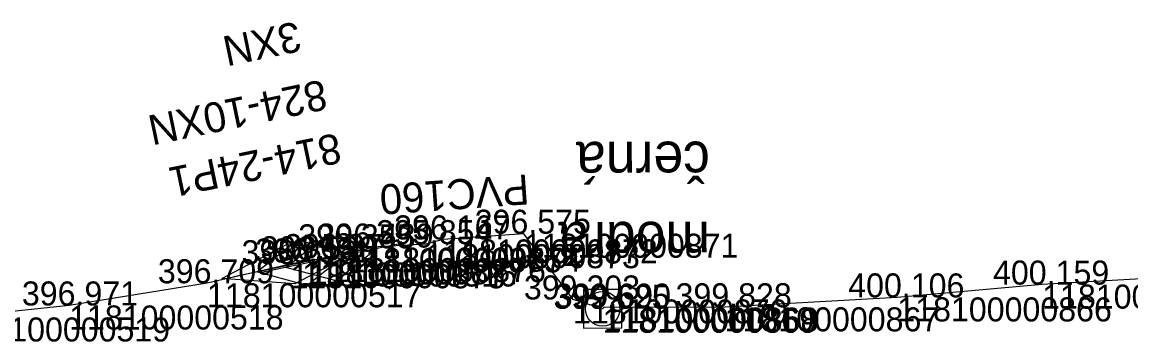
# Model space of a CAD drawing. Extents: x -727171 to -722443, y -945718 to -941834.
# Drawn here: x -723400.7 to -723345.4, y -945339 to -945323 of the extents above; entities that cross this region are included whole.
import ezdxf

# ---------------------------------------------------------------- set-up
doc = ezdxf.new("R2010")
doc.units = 0
for name, color, linetype in [('Vrstva 28', 7, 'Continuous'), ('Vrstva 31', 7, 'Continuous'), ('Vrstva 33', 7, 'Continuous'), ('Vrstva 35', 7, 'Continuous'), ('Vrstva 60', 7, 'Continuous'), ('Vrstva 61', 7, 'Continuous')]:
    doc.layers.add(name, color=color, linetype=linetype)

msp = doc.modelspace()

# ---------------------------------------------------------------- linework, layer by layer
at = {"layer": 'Vrstva 28'}
for p, q in [((-723389.019, -945335.496), (-723386.978, -945333.883)), ((-723387.569, -945335.276), (-723385.528, -945333.663)), ((-723386.978, -945333.883), (-723384.463, -945334.55)), ((-723385.528, -945333.663), (-723383.013, -945334.33)), ((-723383.323, -945334.314), (-723390.159, -945335.732)), ((-723381.873, -945334.094), (-723388.709, -945335.512)), ((-723384.463, -945334.55), (-723386.504, -945336.163)), ((-723383.013, -945334.33), (-723385.054, -945335.943)), ((-723386.504, -945336.163), (-723389.019, -945335.496)), ((-723385.054, -945335.943), (-723387.569, -945335.276))]:
    msp.add_line(p, q, dxfattribs=at)
msp.add_lwpolyline([(-723330.159, -945335.46), (-723333.207, -945336.035), (-723333.428, -945336.077), (-723338.468, -945336.674), (-723341.942, -945335.667), (-723349.803, -945336.126), (-723357.035, -945336.766), (-723365.653, -945337.261), (-723371.687, -945337.277), (-723371.747, -945337.334), (-723373.227, -945336.869), (-723375.679, -945333.586), (-723379.704, -945333.869), (-723380.6, -945334.107), (-723383.538, -945334.276), (-723384.488, -945334.317), (-723385.291, -945334.803), (-723386.372, -945334.912), (-723386.741, -945335.023), (-723387.326, -945335.11), (-723391.5, -945336.06), (-723398.387, -945337.169), (-723404.052, -945337.768)], dxfattribs=at)
at = {"layer": 'Vrstva 31'}
for points in [[(-723330.159, -945335.46), (-723333.207, -945336.035), (-723333.428, -945336.077), (-723338.468, -945336.674), (-723341.942, -945335.667), (-723349.803, -945336.126), (-723357.035, -945336.766), (-723365.653, -945337.261), (-723371.687, -945337.277), (-723371.747, -945337.334), (-723373.227, -945336.869), (-723375.679, -945333.586), (-723379.704, -945333.869), (-723380.6, -945334.107), (-723383.538, -945334.276), (-723384.488, -945334.317), (-723385.291, -945334.803), (-723386.372, -945334.912), (-723387.326, -945335.11), (-723391.5, -945336.06), (-723398.387, -945337.169), (-723404.052, -945337.768)], [(-723383.899, -945334.399), (-723387.123, -945336.089), (-723390.753, -945335.821), (-723387.529, -945334.131), (-723383.899, -945334.399)]]:
    msp.add_lwpolyline(points, dxfattribs=at)
at = {"layer": 'Vrstva 33'}
msp.add_lwpolyline([(-723341.942, -945335.667), (-723349.803, -945336.126), (-723357.035, -945336.766), (-723365.653, -945337.261), (-723371.687, -945337.277), (-723371.747, -945337.334), (-723373.227, -945336.869), (-723375.679, -945333.586), (-723379.704, -945333.869), (-723380.6, -945334.107), (-723383.538, -945334.276), (-723384.488, -945334.317), (-723385.291, -945334.803), (-723386.372, -945334.912), (-723387.326, -945335.11), (-723391.5, -945336.06), (-723398.387, -945337.169), (-723404.052, -945337.768)], dxfattribs=at)
msp.add_lwpolyline([(-723370.79, -945336.371), (-723372.71, -945336.377), (-723372.704, -945338.297), (-723370.784, -945338.291)], close=True, dxfattribs=at)
msp.add_circle((-723371.747, -945337.334), 0.864, dxfattribs=at)
at = {"layer": 'Vrstva 35'}
msp.add_lwpolyline([(-723371.747, -945337.334), (-723373.227, -945336.869), (-723375.679, -945333.586), (-723379.704, -945333.869), (-723380.6, -945334.107), (-723383.538, -945334.276), (-723384.488, -945334.317)], dxfattribs=at)
at = {"layer": 'Vrstva 60'}
for p, q in [((-723379.704, -945333.869), (-723379.704, -945333.869)), ((-723375.679, -945333.586), (-723375.679, -945333.586)), ((-723384.488, -945334.317), (-723384.488, -945334.317)), ((-723383.538, -945334.276), (-723383.538, -945334.276)), ((-723380.6, -945334.107), (-723380.6, -945334.107)), ((-723387.326, -945335.11), (-723387.326, -945335.11)), ((-723386.741, -945335.023), (-723386.741, -945335.023)), ((-723386.372, -945334.912), (-723386.372, -945334.912)), ((-723385.291, -945334.803), (-723385.291, -945334.803)), ((-723391.5, -945336.06), (-723391.5, -945336.06)), ((-723349.803, -945336.126), (-723349.803, -945336.126)), ((-723357.035, -945336.766), (-723357.035, -945336.766)), ((-723398.387, -945337.169), (-723398.387, -945337.169)), ((-723373.227, -945336.869), (-723373.227, -945336.869)), ((-723371.747, -945337.334), (-723371.747, -945337.334)), ((-723371.687, -945337.277), (-723371.687, -945337.277)), ((-723365.653, -945337.261), (-723365.653, -945337.261))]:
    msp.add_line(p, q, dxfattribs=at)

# ---------------------------------------------------------------- texts
at = {"layer": 'Vrstva 28'}
for s, p in [('3XN', (-723386.993, -945322.968)), ('814-24P1', (-723384.986, -945328.543))]:
    msp.add_text(s, height=1.5, rotation=191.7251, dxfattribs=at).set_placement(p)
at = {"layer": 'Vrstva 31'}
msp.add_text('824-10XN', height=1.5, rotation=191.7251, dxfattribs=at).set_placement((-723385.698, -945325.874))
at = {"layer": 'Vrstva 33'}
for s, p in [('černá', (-723366.392, -945328.981)), ('modrá', (-723366.381, -945332.981))]:
    msp.add_text(s, height=2, rotation=180.1519, dxfattribs=at).set_placement(p)
at = {"layer": 'Vrstva 35'}
msp.add_text('PVC160', height=1.5, rotation=184.0219, dxfattribs=at).set_placement((-723375.473, -945330.615))
at = {"layer": 'Vrstva 60'}
for s, p in [('118100000872', (-723379.704, -945335.069)), ('118100000871', (-723375.679, -945334.786)), ('118100000875', (-723384.488, -945335.517)), ('118100000874', (-723383.538, -945335.476)), ('118100000873', (-723380.6, -945335.307)), ('118100000878', (-723387.326, -945336.31)), ('118100000516', (-723386.741, -945336.223)), ('118100000877', (-723386.372, -945336.112)), ('118100000876', (-723385.291, -945336.003)), ('118100000517', (-723391.5, -945337.26)), ('118100000865', (-723349.803, -945337.326)), ('118100000866', (-723357.035, -945337.966)), ('118100000518', (-723398.387, -945338.369)), ('118100000870', (-723373.227, -945338.069)), ('118100000869', (-723371.747, -945338.534)), ('118100000868', (-723371.687, -945338.477)), ('118100000867', (-723365.653, -945338.461)), ('118100000519', (-723404.052, -945338.968))]:
    msp.add_text(s, height=1.2, dxfattribs=at).set_placement(p)
at = {"layer": 'Vrstva 61'}
for s, p in [('396.575', (-723378.135, -945333.586)), ('395.854', (-723383.051, -945334.107)), ('396.167', (-723382.156, -945333.869)), ('396.355', (-723386.944, -945334.317)), ('396.439', (-723385.992, -945334.276)), ('396.613', (-723389.778, -945335.11)), ('396.391', (-723389.098, -945335.023)), ('396.539', (-723388.826, -945334.912)), ('396.371', (-723387.648, -945334.803)), ('396.709', (-723393.954, -945336.06)), ('400.159', (-723352.257, -945336.126)), ('399.203', (-723375.679, -945336.869)), ('400.106', (-723359.487, -945336.766)), ('396.971', (-723400.744, -945337.169)), ('399.625', (-723374.203, -945337.334)), ('399.690', (-723374.138, -945337.277)), ('399.828', (-723368.107, -945337.261))]:
    msp.add_text(s, height=1.2, dxfattribs=at).set_placement(p)

doc.saveas('drawing.dxf')
